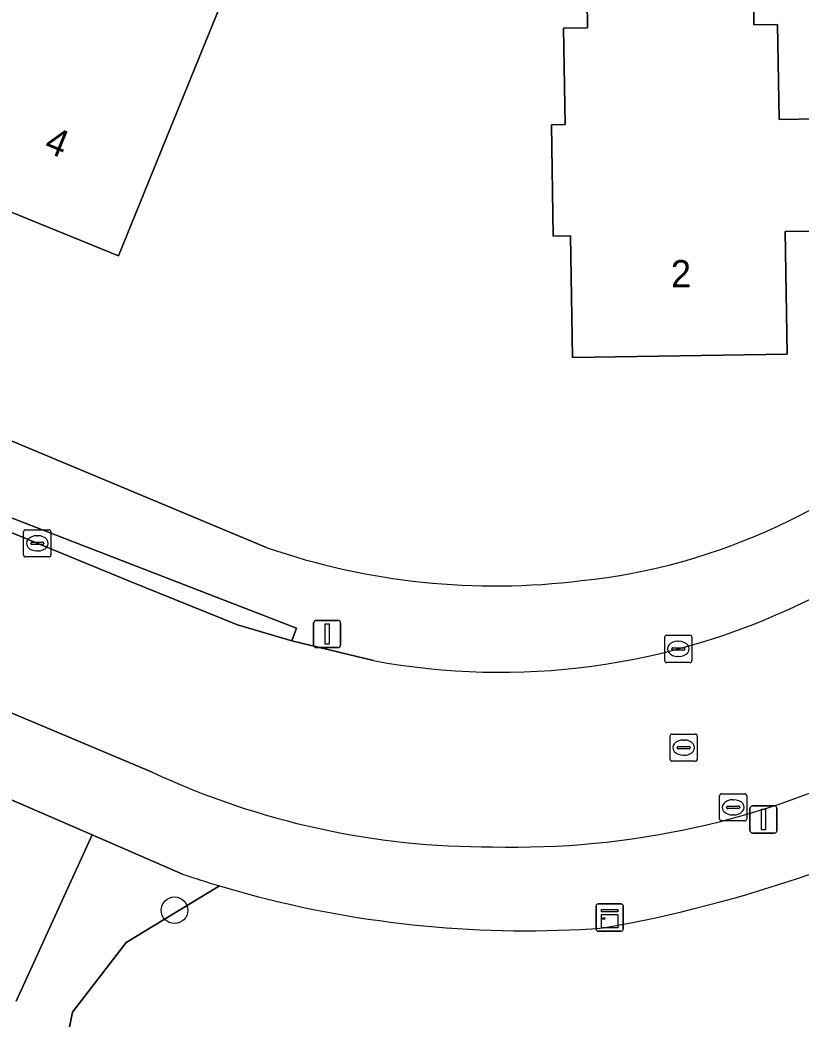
# Model space of a CAD drawing. Extents: x 161139 to 161601, y 381708 to 382245.
# Drawn here: x 161308.44 to 161337.13, y 381862.38 to 381899.09 of the extents above; entities that cross this region are included whole.
import ezdxf

# ---------------------------------------------------------------- set-up
doc = ezdxf.new("R2010")
doc.units = 0
for name, color, linetype in [('IMGEO_Boom', 7, 'Continuous'), ('IMGEO_Erf', 7, 'Continuous'), ('IMGEO_Groenvoorziening', 7, 'Continuous'), ('IMGEO_Kast', 7, 'Continuous'), ('IMGEO_Kolk', 7, 'Continuous'), ('IMGEO_Lichtmast', 7, 'Continuous'), ('IMGEO_Pand', 7, 'Continuous'), ('IMGEO_Pand_nummerreeks', 7, 'Continuous'), ('IMGEO_Rijbaan_lokaal_open', 7, 'Continuous'), ('IMGEO_Rioolput', 7, 'Continuous'), ('IMGEO_Voetpad_halfverhard', 7, 'Continuous'), ('IMGEO_Voetpad_open', 7, 'Continuous')]:
    doc.layers.add(name, color=color, linetype=linetype)

msp = doc.modelspace()

# ---------------------------------------------------------------- linework, layer by layer
at = {"layer": 'IMGEO_Boom'}
msp.add_circle((161314.117, 381866.376), 0.489, dxfattribs=at)
at = {"layer": 'IMGEO_Erf'}
msp.add_lwpolyline([(161316.193, 381910.265), (161323.278, 381907.381), (161321.194, 381902.259), (161317.489, 381903.766), (161313.947, 381895.06), (161312.062, 381890.428), (161305.111, 381893.257), (161305.8, 381894.95), (161305.424, 381895.103), (161305.852, 381896.154), (161306.302, 381895.986), (161306.706, 381897.067), (161302.753, 381898.676), (161306.145, 381907.012), (161310.258, 381905.339), (161309.82, 381904.264), (161313.34, 381902.832), (161314.245, 381905.055), (161314.097, 381905.115)], close=True, dxfattribs=at)
for points in [[(161335.385, 381899.929), (161335.401, 381898.908), (161336.27, 381898.922), (161336.325, 381895.438), (161337.781, 381895.461), (161337.847, 381891.334), (161336.547, 381891.313), (161336.619, 381886.808), (161328.732, 381886.683), (161328.661, 381891.157), (161328.032, 381891.147), (161327.967, 381895.237), (161328.465, 381895.244), (161328.41, 381898.782), (161329.29, 381898.8), (161329.269, 381899.821)], [(161282.757, 381897.162), (161285.416, 381894.897), (161286.952, 381893.797), (161293.664, 381889.876), (161297.982, 381887.859), (161317.522, 381879.697)]]:
    msp.add_lwpolyline(points, dxfattribs=at)
for centre, radius, start, end in [((161326.709, 381900.982), 22.616, 275.9879, 314.2183), ((161325.898, 381903.973), 25.68, 250.9638, 277.0905)]:
    msp.add_arc(centre, radius, start, end, dxfattribs=at)
at = {"layer": 'IMGEO_Groenvoorziening'}
for points in [[(161314.407, 381867.708), (161311.091, 381869.145), (161308.308, 381863.031)], [(161327.068, 381813.921), (161323.551, 381817.064), (161320.271, 381820.654), (161318.036, 381823.431), (161316.053, 381826.383), (161314.232, 381830.46), (161313.259, 381833.868), (161311.903, 381836.939), (161309.5, 381845.894), (161309.428, 381857.979), (161310.374, 381862.638), (161312.34, 381865.186), (161315.768, 381867.273)], [(161315.768, 381867.273), (161312.34, 381865.186), (161310.374, 381862.638), (161309.428, 381857.979), (161309.5, 381845.894), (161311.903, 381836.939), (161313.259, 381833.868), (161314.232, 381830.46), (161316.053, 381826.383), (161318.036, 381823.431), (161320.271, 381820.654), (161323.551, 381817.064), (161327.068, 381813.921)]]:
    msp.add_lwpolyline(points, dxfattribs=at)
for centre, radius, start, end in [((161321.407, 381913.724), 48.737, 279.9868, 298.3875), ((161326.802, 381904.141), 38.483, 251.2115, 253.3389), ((161326.209, 381902.06), 36.321, 253.2937, 254.9911), ((161327.026, 381904.852), 39.228, 254.8945, 274.1416)]:
    msp.add_arc(centre, radius, start, end, dxfattribs=at)
at = {"layer": 'IMGEO_Kast'}
for p, q in [((161329.603, 381865.684), (161329.603, 381866.525)), ((161329.603, 381866.525), (161329.603, 381865.684)), ((161329.678, 381866.609), (161330.519, 381866.609)), ((161330.519, 381866.609), (161329.678, 381866.609)), ((161330.603, 381866.534), (161330.603, 381865.693)), ((161330.603, 381865.693), (161330.603, 381866.534)), ((161330.528, 381865.609), (161329.687, 381865.609)), ((161329.687, 381865.609), (161330.528, 381865.609))]:
    msp.add_line(p, q, dxfattribs=at)
for points in [[(161329.798, 381866.399), (161330.398, 381866.399), (161330.398, 381866.314), (161329.798, 381866.314), (161329.798, 381866.399)], [(161329.798, 381866.224), (161330.398, 381866.224), (161330.398, 381865.735), (161329.798, 381865.735), (161329.798, 381866.224)]]:
    msp.add_lwpolyline(points, dxfattribs=at)
msp.add_circle((161329.882, 381866.073), 0.0377, dxfattribs=at)
for centre, start, end in [((161329.681, 381866.531), 92.4484, 184.2845), ((161329.681, 381866.531), 92.4484, 184.2845), ((161330.525, 381866.531), 2.4484, 94.2845), ((161330.525, 381866.531), 2.4484, 94.2845), ((161329.681, 381865.687), 182.4484, 274.2845), ((161329.681, 381865.687), 182.4484, 274.2845), ((161330.525, 381865.687), 272.4484, 4.2845), ((161330.525, 381865.687), 272.4484, 4.2845)]:
    msp.add_arc(centre, 0.0779, start, end, dxfattribs=at)
at = {"layer": 'IMGEO_Kolk'}
for p, q in [((161308.652, 381880.359), (161309.504, 381880.359)), ((161308.577, 381879.433), (161308.577, 381880.285)), ((161309.065, 381880.139), (161309.09, 381880.139)), ((161309.578, 381880.285), (161309.578, 381879.433)), ((161308.836, 381879.853), (161308.836, 381879.865)), ((161309.274, 381879.816), (161308.876, 381879.816)), ((161308.879, 381879.902), (161309.277, 381879.902)), ((161309.32, 381879.865), (161309.32, 381879.853)), ((161309.504, 381879.359), (161308.652, 381879.359)), ((161309.088, 381879.579), (161309.063, 381879.579)), ((161332.122, 381875.554), (161332.122, 381876.406)), ((161332.197, 381876.48), (161333.049, 381876.48)), ((161333.123, 381876.406), (161333.123, 381875.554)), ((161332.381, 381875.974), (161332.381, 381875.986)), ((161332.819, 381875.937), (161332.421, 381875.937)), ((161332.424, 381876.023), (161332.822, 381876.023)), ((161332.61, 381876.26), (161332.635, 381876.26)), ((161332.865, 381875.986), (161332.865, 381875.974)), ((161332.633, 381875.7), (161332.608, 381875.7)), ((161333.049, 381875.48), (161332.197, 381875.48)), ((161334.137, 381869.732), (161334.137, 381870.584)), ((161334.212, 381870.658), (161335.064, 381870.658)), ((161334.625, 381870.438), (161334.65, 381870.438)), ((161335.138, 381870.584), (161335.138, 381869.732)), ((161334.396, 381870.152), (161334.396, 381870.164)), ((161334.834, 381870.115), (161334.436, 381870.115)), ((161334.439, 381870.201), (161334.837, 381870.201)), ((161334.88, 381870.164), (161334.88, 381870.152)), ((161334.648, 381869.878), (161334.623, 381869.878)), ((161335.064, 381869.658), (161334.212, 381869.658))]:
    msp.add_line(p, q, dxfattribs=at)
for points in [[(161308.652, 381880.359), (161309.504, 381880.359)], [(161308.577, 381879.433), (161308.577, 381880.285)], [(161309.578, 381880.285), (161309.578, 381879.433)], [(161309.504, 381879.359), (161308.652, 381879.359)], [(161332.122, 381875.554), (161332.122, 381876.406)], [(161332.197, 381876.48), (161333.049, 381876.48)], [(161333.123, 381876.406), (161333.123, 381875.554)], [(161333.049, 381875.48), (161332.197, 381875.48)], [(161334.137, 381869.732), (161334.137, 381870.584)], [(161334.212, 381870.658), (161335.064, 381870.658)], [(161335.138, 381870.584), (161335.138, 381869.732)], [(161335.064, 381869.658), (161334.212, 381869.658)]]:
    msp.add_lwpolyline(points, dxfattribs=at)
for centre, radius, start, end in [((161308.654, 381880.283), 0.0765, 91.552, 178.448), ((161308.654, 381880.283), 0.0765, 91.552, 178.448), ((161309.502, 381880.283), 0.0765, 1.552, 88.448), ((161309.502, 381880.283), 0.0765, 1.552, 88.448), ((161308.876, 381879.862), 0.0403, 85.8775, 175.7526), ((161308.873, 381879.852), 0.0366, 178.938, 274.7102), ((161309.277, 381879.859), 0.043, 264.8664, 352.4533), ((161309.281, 381879.864), 0.0386, 1.7309, 96.639), ((161308.654, 381879.435), 0.0765, 181.552, 268.448), ((161308.654, 381879.435), 0.0765, 181.552, 268.448), ((161309.502, 381879.435), 0.0765, 271.552, 358.448), ((161309.502, 381879.435), 0.0765, 271.552, 358.448), ((161332.199, 381876.404), 0.0765, 91.552, 178.448), ((161332.199, 381876.404), 0.0765, 91.552, 178.448), ((161333.047, 381876.404), 0.0765, 1.552, 88.448), ((161333.047, 381876.404), 0.0765, 1.552, 88.448), ((161332.421, 381875.983), 0.0403, 85.8775, 175.7526), ((161332.418, 381875.973), 0.0366, 178.938, 274.7102), ((161332.822, 381875.98), 0.043, 264.8664, 352.4533), ((161332.826, 381875.985), 0.0386, 1.7309, 96.639), ((161332.199, 381875.556), 0.0765, 181.552, 268.448), ((161332.199, 381875.556), 0.0765, 181.552, 268.448), ((161333.047, 381875.556), 0.0765, 271.552, 358.448), ((161333.047, 381875.556), 0.0765, 271.552, 358.448), ((161334.214, 381870.582), 0.0765, 91.552, 178.448), ((161334.214, 381870.582), 0.0765, 91.552, 178.448), ((161335.062, 381870.582), 0.0765, 1.552, 88.448), ((161335.062, 381870.582), 0.0765, 1.552, 88.448), ((161334.436, 381870.161), 0.0403, 85.8775, 175.7526), ((161334.433, 381870.151), 0.0366, 178.938, 274.7102), ((161334.837, 381870.158), 0.043, 264.8664, 352.4533), ((161334.841, 381870.163), 0.0386, 1.7309, 96.639), ((161334.214, 381869.734), 0.0765, 181.552, 268.448), ((161334.214, 381869.734), 0.0765, 181.552, 268.448), ((161335.062, 381869.734), 0.0765, 271.552, 358.448), ((161335.062, 381869.734), 0.0765, 271.552, 358.448)]:
    msp.add_arc(centre, radius, start, end, dxfattribs=at)
for centre, major_axis, ratio, start_param, end_param in [((161309.064, 381879.859), (-0.387, 0.002), 0.722429, 4.712389, 7.853982), ((161309.089, 381879.859), (-0.39, 0.002), 0.717154, 1.570796, 4.712389), ((161332.609, 381875.98), (-0.387, 0.002), 0.722429, 4.712389, 7.853982), ((161332.634, 381875.98), (-0.39, 0.002), 0.717154, 1.570796, 4.712389), ((161334.624, 381870.158), (-0.387, 0.002), 0.722429, 4.712389, 7.853982), ((161334.649, 381870.158), (-0.39, 0.002), 0.717154, 1.570796, 4.712389)]:
    msp.add_ellipse(centre, major_axis=major_axis, ratio=ratio, start_param=start_param, end_param=end_param, dxfattribs=at)
at = {"layer": 'IMGEO_Lichtmast'}
for p, q in [((161319.327, 381877.027), (161320.117, 381877.027)), ((161320.117, 381877.027), (161319.327, 381877.027)), ((161319.227, 381876.127), (161319.227, 381876.927)), ((161319.227, 381876.927), (161319.227, 381876.127)), ((161320.217, 381876.927), (161320.217, 381876.127)), ((161320.217, 381876.127), (161320.217, 381876.927)), ((161320.117, 381876.027), (161319.327, 381876.027)), ((161319.327, 381876.027), (161320.117, 381876.027)), ((161335.253, 381869.312), (161335.253, 381870.112)), ((161335.253, 381870.112), (161335.253, 381869.312)), ((161335.353, 381870.212), (161336.143, 381870.212)), ((161336.143, 381870.212), (161335.353, 381870.212)), ((161336.243, 381870.112), (161336.243, 381869.312)), ((161336.243, 381869.312), (161336.243, 381870.112)), ((161336.143, 381869.212), (161335.353, 381869.212)), ((161335.353, 381869.212), (161336.143, 381869.212))]:
    msp.add_line(p, q, dxfattribs=at)
for points in [[(161319.647, 381876.902), (161319.797, 381876.902), (161319.797, 381876.152), (161319.647, 381876.152), (161319.647, 381876.902)], [(161335.673, 381870.087), (161335.823, 381870.087), (161335.823, 381869.337), (161335.673, 381869.337), (161335.673, 381870.087)]]:
    msp.add_lwpolyline(points, dxfattribs=at)
for centre, start, end in [((161319.327, 381876.927), 90, 180), ((161319.327, 381876.927), 90, 180), ((161320.117, 381876.927), 0, 90), ((161320.117, 381876.927), 360, 90), ((161319.327, 381876.127), 180, 270), ((161319.327, 381876.127), 180, 270), ((161320.117, 381876.127), 270, 0), ((161320.117, 381876.127), 270, 0), ((161335.353, 381870.112), 90, 180), ((161335.353, 381870.112), 90, 180), ((161336.143, 381870.112), 0, 90), ((161336.143, 381870.112), 360, 90), ((161335.353, 381869.312), 180, 270), ((161335.353, 381869.312), 180, 270), ((161336.143, 381869.312), 270, 0), ((161336.143, 381869.312), 270, 0)]:
    msp.add_arc(centre, 0.1, start, end, dxfattribs=at)
at = {"layer": 'IMGEO_Pand'}
msp.add_lwpolyline([(161312.062, 381890.428), (161313.947, 381895.06), (161317.489, 381903.766), (161321.194, 381902.259), (161323.278, 381907.381), (161316.193, 381910.265), (161314.097, 381905.115), (161314.245, 381905.055), (161313.34, 381902.832), (161309.82, 381904.264), (161310.258, 381905.339), (161306.145, 381907.012), (161302.753, 381898.676), (161306.706, 381897.067), (161306.302, 381895.986), (161305.852, 381896.154), (161305.424, 381895.103), (161305.8, 381894.95), (161305.111, 381893.257)], close=True, dxfattribs=at)
msp.add_lwpolyline([(161329.269, 381899.821), (161329.29, 381898.8), (161328.41, 381898.782), (161328.465, 381895.244), (161327.967, 381895.237), (161328.032, 381891.147), (161328.661, 381891.157), (161328.732, 381886.683), (161336.619, 381886.808), (161336.547, 381891.313), (161337.847, 381891.334), (161337.781, 381895.461), (161336.325, 381895.438), (161336.27, 381898.922), (161335.401, 381898.908), (161335.385, 381899.929)], dxfattribs=at)
at = {"layer": 'IMGEO_Rijbaan_lokaal_open'}
for points in [[(161321.429, 381875.549), (161318.426, 381876.273), (161316.431, 381876.868), (161312.405, 381878.498), (161307.913, 381880.338), (161302.959, 381882.345), (161298.323, 381884.279), (161296.095, 381885.289)], [(161297.345, 381878.162), (161313.303, 381871.448)]]:
    msp.add_lwpolyline(points, dxfattribs=at)
for centre, radius, start, end in [((161326.251, 381901.996), 26.667, 294.0744, 313.7929), ((161326.071, 381900.593), 25.471, 259.4991, 295.7309), ((161326.635, 381899.193), 30.495, 268.4215, 296.5025), ((161325.661, 381897.966), 29.257, 245.0131, 270.2617)]:
    msp.add_arc(centre, radius, start, end, dxfattribs=at)
at = {"layer": 'IMGEO_Rioolput'}
for p, q in [((161332.319, 381871.926), (161332.319, 381872.778)), ((161332.394, 381872.852), (161333.246, 381872.852)), ((161332.807, 381872.632), (161332.832, 381872.632)), ((161333.32, 381872.778), (161333.32, 381871.926)), ((161332.578, 381872.346), (161332.578, 381872.358)), ((161333.016, 381872.309), (161332.618, 381872.309)), ((161332.621, 381872.395), (161333.019, 381872.395)), ((161333.062, 381872.358), (161333.062, 381872.346)), ((161332.83, 381872.072), (161332.805, 381872.072)), ((161333.246, 381871.852), (161332.394, 381871.852))]:
    msp.add_line(p, q, dxfattribs=at)
for points in [[(161332.319, 381871.926), (161332.319, 381872.778)], [(161332.394, 381872.852), (161333.246, 381872.852)], [(161333.32, 381872.778), (161333.32, 381871.926)], [(161333.246, 381871.852), (161332.394, 381871.852)]]:
    msp.add_lwpolyline(points, dxfattribs=at)
for centre, radius, start, end in [((161332.396, 381872.776), 0.0765, 91.552, 178.448), ((161332.396, 381872.776), 0.0765, 91.552, 178.448), ((161333.244, 381872.776), 0.0765, 1.552, 88.448), ((161333.244, 381872.776), 0.0765, 1.552, 88.448), ((161332.618, 381872.355), 0.0403, 85.8775, 175.7526), ((161332.615, 381872.345), 0.0366, 178.938, 274.7102), ((161333.019, 381872.352), 0.043, 264.8664, 352.4533), ((161333.023, 381872.357), 0.0386, 1.7309, 96.639), ((161332.396, 381871.928), 0.0765, 181.552, 268.448), ((161332.396, 381871.928), 0.0765, 181.552, 268.448), ((161333.244, 381871.928), 0.0765, 271.552, 358.448), ((161333.244, 381871.928), 0.0765, 271.552, 358.448)]:
    msp.add_arc(centre, radius, start, end, dxfattribs=at)
for centre, major_axis, ratio, start_param, end_param in [((161332.806, 381872.352), (-0.387, 0.002), 0.722429, 4.712389, 7.853982), ((161332.831, 381872.352), (-0.39, 0.002), 0.717154, 1.570796, 4.712389)]:
    msp.add_ellipse(centre, major_axis=major_axis, ratio=ratio, start_param=start_param, end_param=end_param, dxfattribs=at)
at = {"layer": 'IMGEO_Voetpad_halfverhard'}
msp.add_lwpolyline([(161308.308, 381863.031), (161311.091, 381869.145), (161307.156, 381870.851)], dxfattribs=at)
at = {"layer": 'IMGEO_Voetpad_open'}
for points in [[(161317.522, 381879.697), (161297.982, 381887.859), (161293.664, 381889.876), (161286.952, 381893.797), (161285.416, 381894.897), (161282.757, 381897.162)], [(161296.095, 381885.289), (161298.323, 381884.279), (161302.959, 381882.345), (161307.913, 381880.338), (161308.089, 381880.805), (161318.602, 381876.74), (161318.426, 381876.273), (161321.429, 381875.549)], [(161287.109, 381879.723), (161295.616, 381875.775), (161306.308, 381871.219), (161307.156, 381870.851), (161311.091, 381869.145), (161314.407, 381867.708)], [(161313.303, 381871.448), (161297.345, 381878.162)]]:
    msp.add_lwpolyline(points, dxfattribs=at)
msp.add_lwpolyline([(161318.426, 381876.273), (161318.602, 381876.74), (161308.089, 381880.805), (161307.913, 381880.338), (161312.405, 381878.498), (161316.431, 381876.868)], close=True, dxfattribs=at)
for centre, radius, start, end in [((161326.709, 381900.982), 22.616, 275.9879, 314.2183), ((161326.251, 381901.996), 26.667, 294.0744, 313.7929), ((161325.898, 381903.973), 25.68, 250.9638, 277.0905), ((161326.071, 381900.593), 25.471, 259.4991, 295.7309), ((161326.635, 381899.193), 30.495, 268.4215, 296.5025), ((161325.661, 381897.966), 29.257, 245.0131, 270.2617), ((161321.407, 381913.724), 48.737, 279.9868, 298.3875), ((161326.802, 381904.141), 38.483, 251.2115, 253.3389), ((161326.209, 381902.06), 36.321, 253.2937, 254.9911), ((161327.026, 381904.852), 39.228, 254.8945, 274.1416)]:
    msp.add_arc(centre, radius, start, end, dxfattribs=at)

# ---------------------------------------------------------------- texts
at = {"layer": 'IMGEO_Pand_nummerreeks'}
for s, rotation, p in [('4', 337.8541, (161309.282, 381894.281)), ('2', 0.908, (161332.358, 381889.261))]:
    msp.add_text(s, height=1, rotation=rotation, dxfattribs=at).set_placement(p)

doc.saveas('drawing.dxf')
